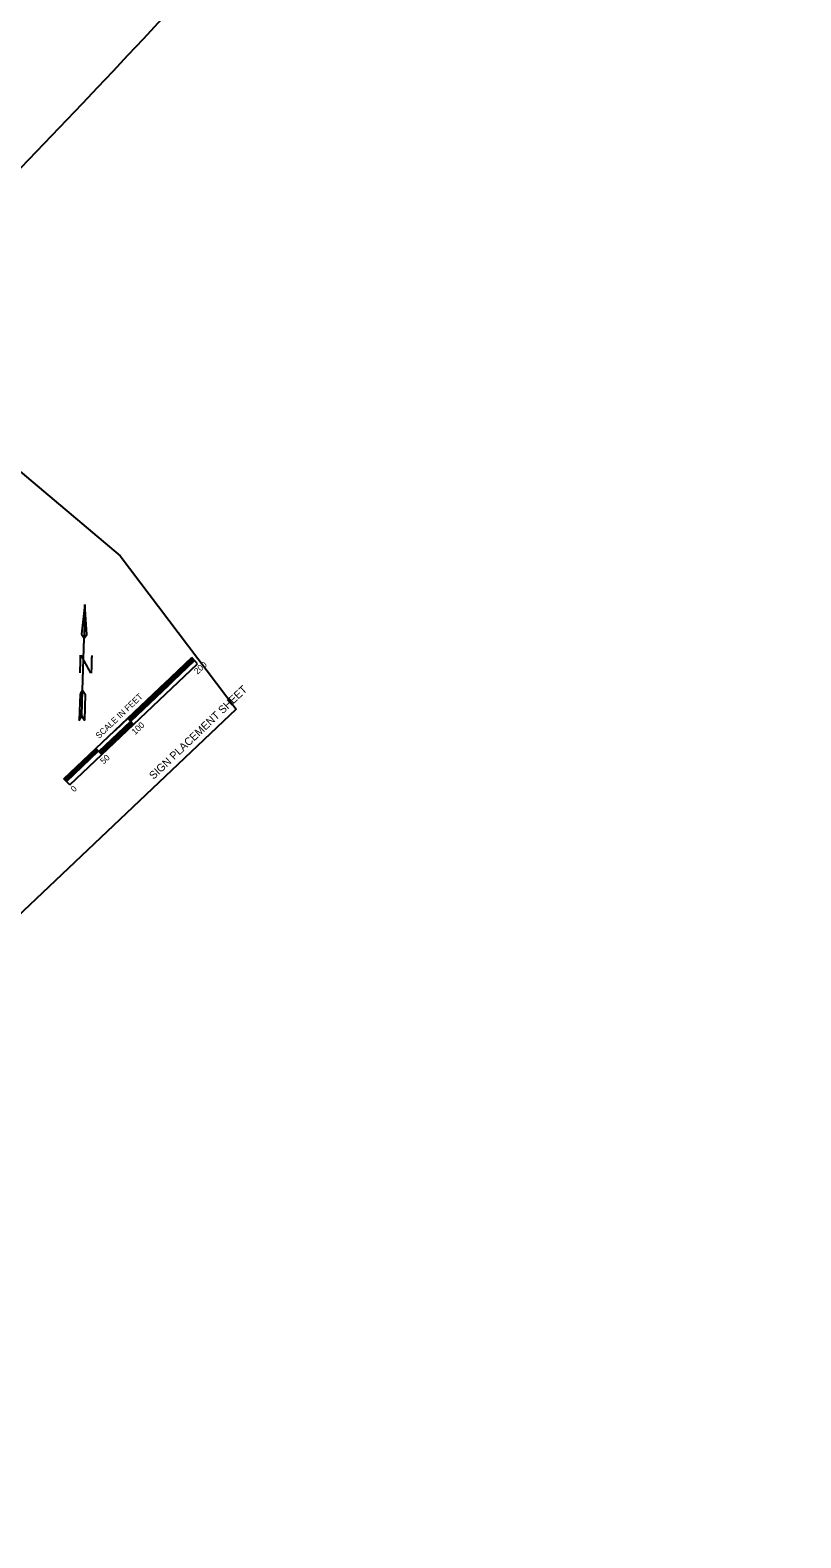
# Model space of a CAD drawing. Extents: x 1289840 to 1295361, y 220865 to 226414.
# Drawn here: x 1294486 to 1295361, y 223828 to 225540 of the extents above; entities that cross this region are included whole.
import ezdxf

# ---------------------------------------------------------------- set-up
doc = ezdxf.new("R2010")
doc.units = 0
for name, color, linetype in [('60', 7, 'Continuous'), ('G-ANNO-TEXT', 7, 'Continuous'), ('Level 10', 7, 'Continuous'), ('R_Drainage', 7, 'Continuous'), ('R_No Plot', 7, 'Continuous')]:
    doc.layers.add(name, color=color, linetype=linetype)

msp = doc.modelspace()

# ---------------------------------------------------------------- linework, layer by layer
at = {"layer": 'G-ANNO-TEXT'}
for p, q in [((1294548.3, 224887.8), (1294544.2, 224853.9)), ((1294544.2, 224853.9), (1294547.3, 224849.3)), ((1294545.7, 224790.5), (1294547.3, 224849.3))]:
    msp.add_line(p, q, dxfattribs=at)
for points in [[(1294548.3, 224887.6), (1294547.3, 224849.3), (1294550.5, 224853.7)], [(1294542.7, 224785.9), (1294541.9, 224756.4), (1294544.9, 224761.2), (1294545.7, 224790.5)], [(1294545.7, 224790.5), (1294548.5, 224785.7), (1294547.7, 224756.3), (1294544.9, 224761.2)]]:
    msp.add_lwpolyline(points, close=True, dxfattribs=at)
at = {"layer": 'Level 10'}
for p, q in [((1294531, 224682.8), (1294676.1, 224820.4)), ((1294582.5, 224744.8), (1294669.5, 224827.4)), ((1294597.5, 224758), (1294670.1, 224826.8)), ((1294598.1, 224757.4), (1294670.6, 224826.2)), ((1294598.6, 224756.8), (1294671.2, 224825.6)), ((1294599.2, 224756.2), (1294671.7, 224825)), ((1294599.7, 224755.7), (1294672.3, 224824.5)), ((1294600.3, 224755.1), (1294672.8, 224823.9)), ((1294676.2, 224820.4), (1294669.6, 224827.4)), ((1294524.4, 224689.8), (1294640.5, 224799.8)), ((1294600.3, 224755.1), (1294643.8, 224796.4)), ((1294564, 224720.7), (1294600.3, 224755.1)), ((1294564.6, 224720.1), (1294600.8, 224754.5)), ((1294565.1, 224719.5), (1294601.4, 224753.9)), ((1294565.7, 224718.9), (1294601.9, 224753.3)), ((1294566.2, 224718.3), (1294602.5, 224752.8)), ((1294566.8, 224717.8), (1294603, 224752.2)), ((1294603.6, 224751.6), (1294597, 224758.6)), ((1294560, 224710.3), (1294589.1, 224737.8)), ((1294524.4, 224689.8), (1294553.4, 224717.3)), ((1294525, 224689.2), (1294561.2, 224723.6)), ((1294525.5, 224688.6), (1294561.8, 224723)), ((1294526.1, 224688), (1294562.3, 224722.4)), ((1294526.6, 224687.4), (1294562.9, 224721.8)), ((1294527.2, 224686.9), (1294563.4, 224721.3)), ((1294567.3, 224717.2), (1294560.7, 224724.2)), ((1294531, 224682.8), (1294524.4, 224689.8))]:
    msp.add_line(p, q, dxfattribs=at)
at = {"layer": 'R_Drainage'}
msp.add_arc((1286302.7, 233302.8), 11380.2, 314.63694, 322.75013, dxfattribs=at)
at = {"layer": 'R_No Plot'}
msp.add_lwpolyline([(1293463.5, 223873.7), (1293451, 223927.3), (1293084.9, 224313.6), (1293049.2, 224285.3), (1292886.4, 224457.1), (1293263.3, 224814.3), (1294021.3, 225526.9), (1294425.8, 225079.3), (1294588.3, 224942.9), (1294719.9, 224769), (1294177.1, 224254.6), (1293865.4, 223959.2), (1293708.8, 223976.9), (1293583.3, 224083.8), (1293485, 224003.9), (1293450.7, 223971.9), (1293580.2, 223892), (1293536.7, 223828.2)], close=True, dxfattribs=at)

# ---------------------------------------------------------------- texts
at = {"layer": '60'}
msp.add_text('SIGN PLACEMENT SHEET', height=8.87, rotation=43.4636, dxfattribs=at).set_placement((1294626.2, 224688.5))
at = {"layer": 'G-ANNO-TEXT'}
msp.add_text('N', height=20.4, rotation=358.4728, dxfattribs=at).set_placement((1294539.3, 224809.9))
at = {"layer": 'Level 10'}
for s, height, p in [('200', 7, (1294676.2, 224807.9)), ('SCALE IN FEET', 7.001, (1294564.3, 224734.8)), ('100', 7, (1294605.3, 224739.2)), ('50', 7, (1294569.6, 224705.9)), ('0', 7, (1294536, 224674.2))]:
    msp.add_text(s, height=height, rotation=43.4774, dxfattribs=at).set_placement(p)

doc.saveas('drawing.dxf')
